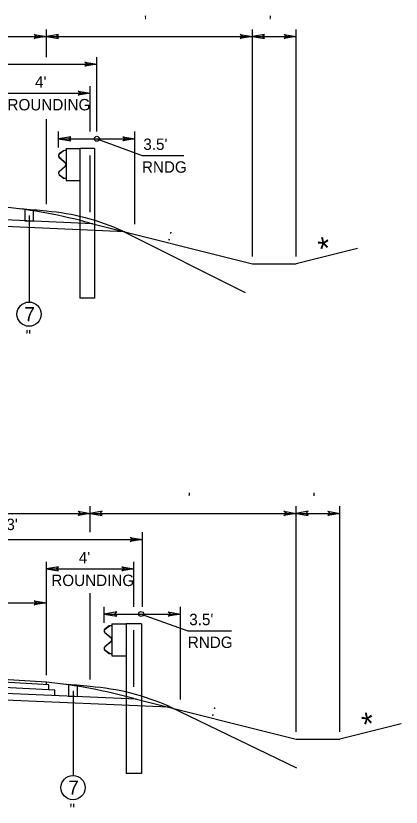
# Model space of a CAD drawing. Extents: x -592 to 1199, y -590 to 416.
# Drawn here: x -281.6 to -234.2, y 53.3 to 150.5 of the extents above; entities that cross this region are included whole.
import ezdxf

# ---------------------------------------------------------------- set-up
doc = ezdxf.new("R2010")
doc.units = 0
doc.layers.add('1', color=7, linetype='Continuous')
doc.layers.add('Des_ Drain_ Ftrs', color=7, linetype='Continuous')

msp = doc.modelspace()

# ---------------------------------------------------------------- linework, layer by layer
at = {"layer": '1'}
for p, q in [((-277.793, 145.454), (-277.793, 148.844)), ((-252.467, 120.951), (-252.467, 148.844)), ((-247.078, 120.951), (-247.078, 148.844)), ((-299.347, 147.964), (-277.793, 147.964)), ((-277.793, 147.964), (-252.467, 147.964)), ((-252.467, 147.964), (-247.078, 147.964)), ((-271.59, 136.298), (-271.59, 145.454)), ((-299.34, 144.574), (-271.59, 144.574)), ((-283.183, 141.003), (-272.407, 141.003)), ((-272.407, 136.298), (-272.407, 141.883)), ((-277.793, 127.39), (-277.793, 137.813)), ((-276.282, 134.347), (-276.282, 136.298)), ((-266.898, 124.934), (-266.898, 136.298)), ((-276.282, 135.418), (-266.898, 135.418)), ((-271.59, 135.418), (-266.033, 133.347)), ((-275.37, 134.234), (-275.37, 130.303)), ((-275.37, 134.234), (-273.685, 134.234)), ((-273.685, 134.234), (-273.685, 115.837)), ((-271.859, 134.234), (-273.685, 134.234)), ((-271.859, 134.234), (-271.859, 115.837)), ((-275.684, 133.95), (-276.201, 133.561)), ((-276.197, 133.151), (-275.466, 132.516)), ((-275.672, 133.922), (-276.183, 133.538)), ((-275.37, 134.006), (-275.684, 133.95)), ((-275.37, 133.976), (-275.672, 133.922)), ((-272.407, 126.423), (-272.407, 133.379)), ((-266.033, 133.347), (-260.878, 133.347)), ((-276.216, 133.129), (-275.485, 132.494)), ((-275.399, 132.306), (-275.399, 132.231)), ((-275.37, 132.306), (-275.37, 132.231)), ((-275.485, 132.043), (-276.216, 131.408)), ((-275.466, 132.02), (-276.197, 131.385)), ((-276.201, 130.975), (-275.684, 130.586)), ((-276.183, 130.999), (-275.672, 130.614)), ((-275.684, 130.586), (-275.37, 130.53)), ((-275.672, 130.614), (-275.37, 130.56)), ((-275.37, 130.303), (-273.685, 130.303)), ((-272.07, 124.972), (-326.288, 127.339)), ((-279.922, 126.014), (-279.922, 115.363)), ((-276.282, 126.288), (-276.282, 126.288)), ((-268.149, 123.992), (-297.7, 125.282)), ((-272.407, 125.056), (-252.467, 120.071)), ((-268.398, 124.054), (-253.347, 116.529)), ((-239.543, 121.955), (-247.078, 120.071)), ((-252.467, 120.071), (-247.078, 120.071)), ((-271.859, 115.837), (-273.685, 115.837)), ((-299.349, 89.417), (-272.407, 89.417)), ((-272.407, 87.087), (-272.407, 90.297)), ((-272.407, 89.417), (-247.089, 89.417)), ((-247.089, 62.571), (-247.089, 90.297)), ((-247.089, 89.417), (-241.701, 89.417)), ((-241.701, 62.571), (-241.701, 90.297)), ((-265.982, 77.933), (-265.982, 87.089)), ((-299.351, 86.209), (-265.982, 86.209)), ((-277.797, 69.563), (-277.797, 83.469)), ((-267.021, 77.933), (-267.021, 83.469)), ((-277.797, 82.589), (-267.021, 82.589)), ((-272.407, 69.023), (-272.407, 79.632)), ((-299.349, 78.417), (-277.797, 78.417)), ((-270.674, 75.982), (-270.674, 77.933)), ((-261.29, 66.569), (-261.29, 77.933)), ((-270.674, 77.053), (-261.29, 77.053)), ((-266.157, 77.053), (-260.392, 74.982)), ((-269.727, 75.869), (-269.727, 71.938)), ((-269.727, 75.869), (-267.979, 75.869)), ((-267.979, 75.869), (-267.979, 57.472)), ((-266.086, 75.869), (-267.979, 75.869)), ((-266.086, 75.869), (-266.086, 57.472)), ((-270.053, 75.585), (-270.59, 75.196)), ((-270.041, 75.557), (-270.571, 75.173)), ((-269.727, 75.641), (-270.053, 75.585)), ((-269.727, 75.611), (-270.041, 75.557)), ((-267.021, 68.112), (-267.021, 75.087)), ((-260.392, 74.982), (-255.045, 74.982)), ((-270.605, 74.764), (-269.846, 74.129)), ((-270.585, 74.786), (-269.827, 74.151)), ((-269.758, 73.941), (-269.758, 73.866)), ((-269.727, 73.941), (-269.727, 73.866)), ((-269.846, 73.678), (-270.605, 73.043)), ((-269.827, 73.655), (-270.585, 73.02)), ((-270.59, 72.61), (-270.053, 72.221)), ((-270.571, 72.634), (-270.041, 72.249)), ((-270.053, 72.221), (-269.727, 72.165)), ((-270.041, 72.249), (-269.727, 72.195)), ((-269.727, 71.938), (-267.979, 71.938)), ((-266.699, 66.593), (-326.29, 69.195)), ((-277.797, 68.683), (-299.344, 69.935)), ((-277.493, 68.365), (-299.109, 69.626)), ((-276.766, 67.717), (-298.402, 68.787)), ((-277.797, 68.383), (-277.797, 68.683)), ((-277.493, 67.753), (-277.493, 68.365)), ((-262.772, 65.612), (-297.702, 67.138)), ((-276.766, 67.033), (-276.766, 67.717)), ((-274.517, 67.626), (-274.517, 57.219)), ((-270.674, 67.923), (-270.674, 67.923)), ((-267.021, 66.674), (-247.089, 61.691)), ((-262.67, 65.689), (-247.058, 58.164)), ((-234.166, 63.575), (-241.701, 61.691)), ((-247.089, 61.691), (-241.701, 61.691)), ((-266.086, 57.472), (-267.979, 57.472))]:
    msp.add_line(p, q, dxfattribs=at)
for points in [[(-279.367, 125.301), (-279.367, 126.62), (-280.46, 126.785), (-280.46, 125.346)], [(-275.061, 66.961), (-273.956, 66.912), (-273.958, 68.233), (-275.061, 68.395)]]:
    msp.add_lwpolyline(points, close=True, dxfattribs=at)
for centre, radius in [((-271.59, 135.418), 0.3), ((-279.922, 113.878), 1.485), ((-274.517, 55.733), 1.485)]:
    msp.add_circle(centre, radius, dxfattribs=at)
for centre, radius, start, end in [((-276.034, 133.339), 0.278, 126.97989, 229.02099), ((-276.034, 133.339), 0.249, 126.97989, 229.02099), ((-275.648, 132.306), 0.249, 0, 49.03649), ((-275.648, 132.23), 0.249, 310.96352, 0), ((-275.648, 132.306), 0.278, 0, 49.03649), ((-275.648, 132.23), 0.278, 310.96352, 0), ((-276.034, 131.198), 0.278, 130.97902, 233.02011), ((-276.034, 131.198), 0.249, 130.97902, 233.02011), ((-290.066, 60.231), 67.188, 74.76191, 84.12047), ((-288.605, 25.845), 101.244, 83.86333, 85.67746), ((-279.905, 99.223), 27.368, 65.13739, 85.55132), ((-284.682, 1.849), 67.188, 74.75976, 84.11833)]:
    msp.add_arc(centre, radius, start, end, dxfattribs=at)
msp.add_ellipse((-266.157, 77.053), major_axis=(-0.311, 0), ratio=0.964041, dxfattribs=at)
for centre, major_axis, start_param, end_param in [((-270.416, 74.974), (-0.288, 0), 5.35781, 7.138763), ((-270.416, 74.974), (-0.258, 0), 5.35781, 7.138763), ((-270.015, 73.941), (0.258, 0), 0, 0.855848), ((-270.015, 73.865), (0.258, 0), 5.427337, 6.283185), ((-270.015, 73.941), (0.288, 0), 0, 0.855848), ((-270.015, 73.865), (0.288, 0), 5.427337, 6.283185), ((-270.416, 72.832), (-0.288, 0), 5.427608, 7.208561), ((-270.416, 72.832), (-0.258, 0), 5.427608, 7.208561), ((-283.631, -32.521), (105.02, 0), 1.463691, 1.495354), ((-274.606, 40.857), (28.389, 0), 1.136862, 1.493152)]:
    msp.add_ellipse(centre, major_axis=major_axis, ratio=0.964041, start_param=start_param, end_param=end_param, dxfattribs=at)
at = {"layer": 'Des_ Drain_ Ftrs'}
for points in [[(-277.793, 147.964), (-279.282, 147.716), (-278.987, 147.964), (-279.282, 148.213)], [(-277.793, 147.964), (-276.305, 147.716), (-276.6, 147.964), (-276.305, 148.213)], [(-252.467, 147.964), (-253.955, 147.716), (-253.66, 147.964), (-253.955, 148.213)], [(-252.467, 147.964), (-250.978, 147.716), (-251.273, 147.964), (-250.978, 148.213)], [(-247.078, 147.964), (-248.566, 147.716), (-248.271, 147.964), (-248.566, 148.213)], [(-271.59, 144.574), (-273.079, 144.326), (-272.784, 144.574), (-273.079, 144.823)], [(-272.407, 141.003), (-273.895, 140.755), (-273.6, 141.003), (-273.895, 141.251)], [(-276.282, 135.418), (-274.794, 135.17), (-275.089, 135.418), (-274.794, 135.667)], [(-266.898, 135.418), (-268.387, 135.17), (-268.092, 135.418), (-268.387, 135.667)], [(-272.407, 89.417), (-273.896, 89.168), (-273.601, 89.417), (-273.896, 89.665)], [(-272.407, 89.417), (-270.919, 89.168), (-271.214, 89.417), (-270.919, 89.665)], [(-247.089, 89.417), (-248.578, 89.168), (-248.283, 89.417), (-248.578, 89.665)], [(-247.089, 89.417), (-245.601, 89.168), (-245.896, 89.417), (-245.601, 89.665)], [(-241.701, 89.417), (-243.19, 89.168), (-242.895, 89.417), (-243.19, 89.665)], [(-265.982, 86.209), (-267.471, 85.961), (-267.176, 86.209), (-267.471, 86.458)], [(-277.797, 82.589), (-276.309, 82.341), (-276.604, 82.589), (-276.309, 82.838)], [(-267.021, 82.589), (-268.509, 82.341), (-268.214, 82.589), (-268.509, 82.838)], [(-277.797, 78.417), (-279.286, 78.169), (-278.991, 78.417), (-279.286, 78.666)], [(-270.674, 77.053), (-269.13, 76.805), (-269.436, 77.053), (-269.13, 77.302)], [(-261.29, 77.053), (-262.833, 76.805), (-262.527, 77.053), (-262.833, 77.302)]]:
    msp.add_lwpolyline(points, close=True, dxfattribs=at)

# ---------------------------------------------------------------- texts
at = {"layer": '1'}
for s, height, p in [("  '", 1.4, (-266.826, 149.116)), (" '", 1.4, (-250.967, 149.116)), ("4'", 1.4, (-279.185, 141.703)), ('ROUNDING', 1.4, (-282.574, 138.903)), ("3.5'", 1.4, (-265.874, 134.047)), ('RNDG', 1.4, (-266.043, 131.247)), ('7', 1.75, (-280.512, 113.003)), (' "', 1.4, (-280.865, 110.518)), ("  '", 1.4, (-261.444, 90.568)), (" '", 1.4, (-245.59, 90.568)), ("12.3'", 1.4, (-285.31, 87.36)), ("4'", 1.4, (-273.799, 83.289)), ('ROUNDING', 1.4, (-277.188, 80.489)), ("3.5'", 1.4, (-260.227, 75.682)), ('RNDG', 1.4, (-260.403, 72.882)), ('7', 1.75, (-275.108, 54.858)), (' "', 1.4, (-275.46, 52.374))]:
    msp.add_text(s, height=height, dxfattribs=at).set_placement(p)
for s, height, rotation, p in [(' : ', 1.4, 345.77179, (-263.486, 123.116)), ('*', 2.8, 12.84793, (-243.988, 120.425)), (' : ', 1.4, 345.77179, (-258.105, 64.735)), ('*', 2.8, 12.84793, (-238.611, 62.045))]:
    msp.add_text(s, height=height, rotation=rotation, dxfattribs=at).set_placement(p)

doc.saveas('drawing.dxf')
